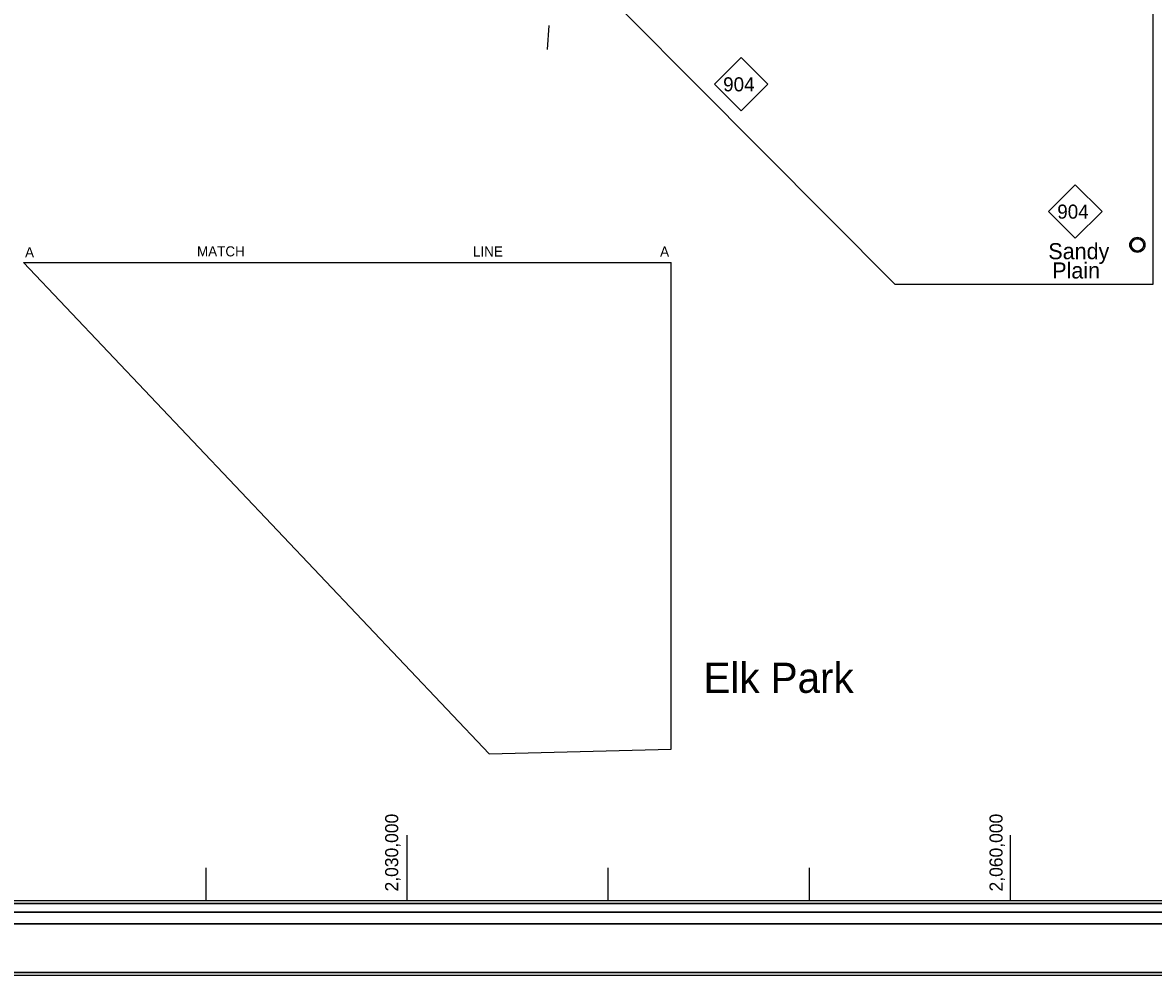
# Model space of a CAD drawing. Extents: x 5197761 to 5514561, y 1890130 to 2080942.
# Drawn here: x 5241653 to 5297901, y 1890130 to 1937547 of the extents above; entities that cross this region are included whole.
import ezdxf

# ---------------------------------------------------------------- set-up
doc = ezdxf.new("R2010")
doc.units = 0
for name, color, linetype in [('Exist Civil Demographics Community CELL', 7, 'Continuous'), ('Exist Civil Demographics Community Label', 7, 'Continuous'), ('Exist Road Primary NC Shield CELL', 7, 'Continuous'), ('Exist Road Primary NC Shield Number Label', 7, 'Continuous'), ('Map Preparation Base StatePlane Tick Label', 7, 'Continuous'), ('Map Preparation Base StatePlane Tick Mark', 7, 'Continuous'), ('Map Preparation Border Antique Large Shape', 7, 'Continuous'), ('Map Preparation Border Antique Small Shape', 7, 'Continuous'), ('Map Preparation Border Black Inside Shape', 7, 'Continuous'), ('Map Preparation Border Black Middle Shape', 7, 'Continuous'), ('Map Preparation Border Black Outside Shape', 7, 'Continuous'), ('Map Preparation County Inset Label', 7, 'Continuous'), ('Map Preparation County Match Line', 7, 'Continuous'), ('Map Preparation County Match Line Label', 7, 'Continuous'), ('Map Preparation Destination Label', 7, 'Continuous'), ('Map Preparation Inset Border', 7, 'Continuous'), ('Map Preparation Inset Cut Line', 7, 'Continuous')]:
    doc.layers.add(name, color=color, linetype=linetype)

msp = doc.modelspace()

# ---------------------------------------------------------------- linework, layer by layer
at = {"layer": 'Exist Civil Demographics Community CELL'}
msp.add_lwpolyline([(5296795, 1926536), (5296799, 1926558), (5296806, 1926585), (5296818, 1926613), (5296830, 1926636), (5296843, 1926659), (5296858, 1926680), (5296874, 1926697), (5296892, 1926716), (5296914, 1926734), (5296936, 1926749), (5296956, 1926760), (5296976, 1926770), (5296998, 1926779), (5297020, 1926787), (5297038, 1926791), (5297057, 1926794), (5297073, 1926797), (5297099, 1926798), (5297117, 1926798), (5297139, 1926797), (5297159, 1926794), (5297178, 1926790), (5297199, 1926784), (5297219, 1926776), (5297246, 1926765), (5297271, 1926751), (5297291, 1926736), (5297312, 1926720), (5297325, 1926708), (5297341, 1926690), (5297357, 1926672), (5297369, 1926653), (5297382, 1926633), (5297392, 1926612), (5297400, 1926592), (5297406, 1926572), (5297411, 1926554), (5297415, 1926530), (5297418, 1926511), (5297419, 1926487), (5297418, 1926464), (5297416, 1926441), (5297412, 1926419), (5297406, 1926395), (5297398, 1926371), (5297389, 1926351), (5297376, 1926327), (5297363, 1926306), (5297349, 1926287), (5297333, 1926268), (5297311, 1926248), (5297291, 1926232), (5297271, 1926218), (5297254, 1926208), (5297227, 1926195), (5297198, 1926184), (5297174, 1926178), (5297148, 1926173), (5297130, 1926171), (5297112, 1926170), (5297090, 1926170), (5297073, 1926172), (5297050, 1926175), (5297027, 1926180), (5297008, 1926185), (5296988, 1926193), (5296969, 1926200), (5296953, 1926209), (5296926, 1926226), (5296904, 1926243), (5296884, 1926261), (5296866, 1926280), (5296854, 1926296), (5296842, 1926313), (5296825, 1926341), (5296819, 1926355), (5296812, 1926371), (5296801, 1926404), (5296795, 1926432), (5296792, 1926453), (5296791, 1926478), (5296791, 1926497), (5296793, 1926523)], close=True, dxfattribs=at)
for centre, radius in [((5297106, 1926486), 377), ((5297105, 1926487), 307)]:
    msp.add_circle(centre, radius, dxfattribs=at)
at = {"layer": 'Exist Road Primary NC Shield CELL'}
for points in [[(5276063, 1934483), (5277395, 1935815), (5278727, 1934483), (5277395, 1933151)], [(5292683, 1928149), (5294015, 1929481), (5295347, 1928149), (5294015, 1926817)]]:
    msp.add_lwpolyline(points, close=True, dxfattribs=at)
at = {"layer": 'Map Preparation Base StatePlane Tick Mark'}
for p, q in [((5260787, 1893858), (5260787, 1897109)), ((5290787, 1893858), (5290787, 1897109)), ((5250787, 1893858), (5250787, 1895484)), ((5270787, 1893858), (5270787, 1895484)), ((5280787, 1893858), (5280787, 1895484))]:
    msp.add_line(p, q, dxfattribs=at)
at = {"layer": 'Map Preparation Border Antique Large Shape'}
msp.add_lwpolyline([(5197907, 2074783), (5207205, 2074783), (5207205, 1892697), (5512539, 1892697), (5512539, 2072359), (5207205, 2072359), (5207205, 2074783), (5514414, 2074783), (5514414, 1890276), (5197907, 1890276)], close=True, dxfattribs=at)
at = {"layer": 'Map Preparation Border Antique Small Shape'}
msp.add_lwpolyline([(5207791, 2071720), (5208220, 2071720), (5208220, 1893712), (5511524, 1893712), (5511524, 2071291), (5208220, 2071291), (5208220, 2071720), (5207791, 2071720), (5511953, 2071720), (5511953, 1893283), (5208220, 1893283), (5207791, 1893283)], close=True, dxfattribs=at)
at = {"layer": 'Map Preparation Border Black Inside Shape'}
msp.add_lwpolyline([(5208220, 2071291), (5511524, 2071291), (5511524, 1893712), (5208366, 1893712), (5208366, 1893858), (5511378, 1893858), (5511378, 2071145), (5208366, 2071145), (5208366, 1893858), (5208366, 1893712), (5208220, 1893712), (5208220, 1893858)], close=True, dxfattribs=at)
at = {"layer": 'Map Preparation Border Black Middle Shape'}
msp.add_lwpolyline([(5207205, 2072359), (5512539, 2072359), (5512539, 1892697), (5511953, 1892697), (5207791, 1892697), (5207791, 1893283), (5511953, 1893283), (5511953, 2071720), (5207791, 2071720), (5207791, 1892697), (5207205, 1892697)], close=True, dxfattribs=at)
at = {"layer": 'Map Preparation Border Black Outside Shape'}
msp.add_lwpolyline([(5197761, 2074930), (5514561, 2074930), (5514561, 1890130), (5197907, 1890130), (5197907, 1890276), (5514414, 1890276), (5514414, 2074783), (5197907, 2074783), (5197907, 1890130), (5197761, 1890130)], close=True, dxfattribs=at)
at = {"layer": 'Map Preparation County Match Line'}
msp.add_line((5241693, 1925605), (5273920, 1925605), dxfattribs=at)
at = {"layer": 'Map Preparation Destination Label'}
msp.add_line((5267759, 1936206), (5267839, 1937407), dxfattribs=at)
at = {"layer": 'Map Preparation Inset Border'}
msp.add_lwpolyline([(5241693, 1925605), (5264861, 1901155), (5273920, 1901395), (5273920, 1925605)], dxfattribs=at)
at = {"layer": 'Map Preparation Inset Cut Line'}
msp.add_lwpolyline([(5261827, 1961312), (5297879, 1961312), (5297879, 1924513), (5285058, 1924513), (5261827, 1947884)], close=True, dxfattribs=at)

# ---------------------------------------------------------------- texts
at = {"layer": 'Exist Civil Demographics Community Label'}
for s, p in [('Sandy', (5292675, 1925772)), ('Plain', (5292870, 1924812))]:
    msp.add_text(s, height=800, dxfattribs=at).set_placement(p)
at = {"layer": 'Exist Road Primary NC Shield Number Label'}
for p in [(5276500, 1934125), (5293120, 1927790)]:
    msp.add_text('904', height=700, dxfattribs=at).set_placement(p)
at = {"layer": 'Map Preparation Base StatePlane Tick Label'}
for s, p in [('2,030,000', (5260335, 1894307)), ('2,060,000', (5290400, 1894307))]:
    msp.add_text(s, height=650, rotation=90, dxfattribs=at).set_placement(p)
at = {"layer": 'Map Preparation County Inset Label'}
msp.add_text('Elk Park', height=1500, dxfattribs=at).set_placement((5275523, 1904190))
at = {"layer": 'Map Preparation County Match Line Label'}
for s, p in [('A', (5241776, 1925869)), ('MATCH', (5250328, 1925912)), ('LINE', (5264054, 1925906)), ('A', (5273364, 1925906))]:
    msp.add_text(s, height=500, rotation=360, dxfattribs=at).set_placement(p)

doc.saveas('drawing.dxf')
